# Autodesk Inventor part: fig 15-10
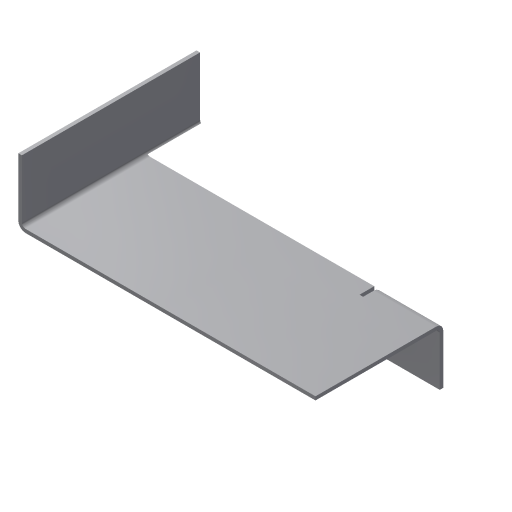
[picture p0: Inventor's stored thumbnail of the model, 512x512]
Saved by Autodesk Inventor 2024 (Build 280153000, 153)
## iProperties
Shininess: 77.0
Angle Display Precision: 2
Document Length Units: 11269
Document Angle Units: 11279
Document Time Units: 11290
Document Mass Units: 11283
Document Length Units Precision: 3
Document Angle Units Precision: 2
Created: 2002-04
Part Number: fig 15-10
Material: Aluminum-6061
Document SubType Name: Sheet Metal
Density: 1 g/cm^3
Sheet Metal Rule: Default
Appearance: Aluminum - Flat-1
Density: 0.0
Volumn: 0.0
Area: 0.0
PropertySet Name: Model Information
Control State: 0
Master: False
Checked Out: False
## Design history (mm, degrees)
node "Face1"
  sketch "Sketch1"
    geometry: L1 (-49.559, 19.574)-(-49.559, -30.426); L2 (-49.559, -30.426)-(50.441, -30.426); L3 (50.441, -30.426)-(50.441, 19.574); L4 (50.441, 19.574)-(32.941, 19.574); L5 (32.941, 19.574)-(32.941, 4.574); L6 (32.941, 4.574)-(-32.059, 4.574); L7 (-32.059, 4.574)-(-32.059, 19.574); L8 (-32.059, 19.574)-(-49.559, 19.574)
    constraints: 16 end point, 6 parallel, 2 equal length, 1 perpendicular, 1 vertical
    dimensions: "d0" = 100 distance of L1.end L2.end; "d1" = 65 distance of L5.end L6.end; "d2" = 15 distance of L6.end L7.end; "d3" = 50 distance of L1.start L1.end
feature "Fold2" dims "d8" = 1 (= BendRadius), "d9" = 90 deg, "d10" = 1 (= BendRadius), "d14" = 1 (= BendReliefWidth), "d15" = 0.5 (= BendReliefDepth), "d16" = 2 (= MinimumRemnant), "d20" = 1 (= Thickness), "SeamGap" = 0.01
feature "Fold3" dims "d11" = 1 (= BendRadius), "d12" = 90 deg, "d13" = 1 (= BendRadius), "d17" = 1, "d18" = 3, "d19" = 2 (= MinimumRemnant), "d20" = 1 (= Thickness), "SeamGap" = 0.01
body "Solid1"
sketch "Sketch2"
  geometry: L1 (100, 0)-(0, 0) reference; L2 (17.5, 50)-(17.5, 35) reference; L3 (82.5, 50)-(82.5, 0)
  constraints: 2 end point, 1 parallel, 1 point on line
face "Plate1" dims "d20" = 1 (= Thickness)
sketch "Sketch3"
  geometry: L1 (81.369, -50)-(0, -50) reference; L2 (17.5, 0)-(17.5, -50)
  constraints: 2 end point, 1 perpendicular, 1 point on line
sketch "Sketch4"
  geometry: L1 (17.5, 0)-(17.5, -50) reference; L2 (-63.869, -15)-(0, -15) reference; L3 (0, -15)-(17.5, -15)
  constraints: 2 end point, 1 collinear, 1 point on line
other parameters: "Thickness" = 1, "BendRadius" = 1 (= Thickness), "BendReliefWidth" = 1 (= Thickness), "BendReliefDepth" = 0.5 (= 0.5 x Thickness), "CornerReliefSize" = 4 (= 4 x Thickness), "MinimumRemnant" = 2 (= 2 x Thickness), "TransitionRadius" = 1 (= BendRadius), "d4" = 1 (= BendRadius), "JacobiRadiusSize" = 1 (= Thickness), "GapSize" = 1 (= Thickness)
